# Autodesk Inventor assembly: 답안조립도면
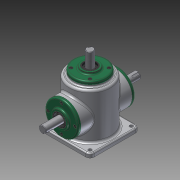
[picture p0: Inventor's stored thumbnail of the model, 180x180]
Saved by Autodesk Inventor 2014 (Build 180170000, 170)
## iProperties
Created: 2015-10
Part Number: 답안조립도면
Document SubType Name: Assembly
Designer: USER
Author: USER
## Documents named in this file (14)
- C:\Users\USER\Desktop\451007V1012\답안조립도면.iam
- C:\Users\USER\Desktop\451007V1012\본체.ipt
- C:\Users\USER\Desktop\451007V1012\M4.ipt
- C:\Users\USER\Desktop\451007V1012\메인 베벨기어.ipt
- C:\Users\USER\Desktop\451007V1012\메인 축.ipt
- 메인 축.ipt
- C:\Users\USER\Desktop\451007V1012\베어링 6203.ipt
- C:\Users\USER\Desktop\451007V1012\서브 베벨기어.ipt
- C:\Users\USER\Desktop\451007V1012\서브 축.ipt
- 서브 축.ipt
- C:\Users\USER\Desktop\451007V1012\오일실.ipt
- C:\Users\USER\Desktop\451007V1012\커버.ipt
- C:\Users\USER\Desktop\451007V1012\키 4x4.ipt
- C:\Users\USER\Desktop\451007V1012\키 5x5.ipt
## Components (12 placed, 1 different names)
1. M4:1
2. M4:4
3. M4:5
4. M4:6
5. M4:2
6. M4:7
7. M4:8
8. M4:9
9. M4:3
10. M4:10
11. M4:11
12. M4:12
